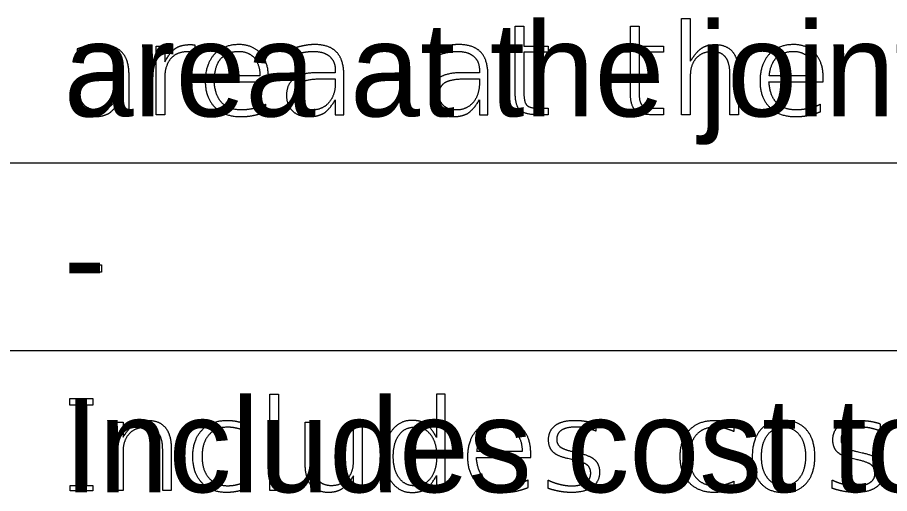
# Model space of a CAD drawing. Extents: x 0.11 to 2.72, y -0.17 to 1.89.
# Drawn here: x 1.1207 to 1.2367, y 1.339 to 1.4023 of the extents above; entities that cross this region are included whole.
import ezdxf

# ---------------------------------------------------------------- set-up
doc = ezdxf.new("R2010")
doc.units = 0
doc.layers.add('SheetGridMinor', color=7, linetype='Continuous')
doc.layers.add('SheetText', color=7, linetype='Continuous')

msp = doc.modelspace()

# ---------------------------------------------------------------- linework, layer by layer
at = {"layer": 'SheetGridMinor'}
for p, q in [((0.15035, 1.38302), (1.94912, 1.38302)), ((0.15035, 1.35802), (1.94912, 1.35802))]:
    msp.add_line(p, q, dxfattribs=at)
at = {"layer": 'SheetText'}
for p, q in [((1.14429, 1.39869), (1.14429, 1.39763)), ((1.12861, 1.39814), (1.12861, 1.3972)), ((1.15719, 1.39814), (1.15719, 1.3972)), ((1.17637, 1.39814), (1.17637, 1.3972)), ((1.15295, 1.39459), (1.14692, 1.39458)), ((1.22677, 1.39459), (1.22074, 1.39458)), ((1.15373, 1.38981), (1.15373, 1.39079)), ((1.22755, 1.38981), (1.22755, 1.39079)), ((1.22263, 1.34874), (1.22263, 1.34874)), ((1.15114, 1.34822), (1.15114, 1.34725)), ((1.19764, 1.34829), (1.19764, 1.34731)), ((1.216, 1.34822), (1.216, 1.34725)), ((1.22263, 1.34783), (1.22263, 1.34783)), ((1.23547, 1.34829), (1.23547, 1.34731)), ((1.1707, 1.34394), (1.1707, 1.34394)), ((1.18785, 1.34459), (1.18183, 1.34458)), ((1.19471, 1.34456), (1.19525, 1.34444)), ((1.23254, 1.34456), (1.23308, 1.34444)), ((1.19448, 1.34353), (1.19394, 1.34366)), ((1.23231, 1.34353), (1.23177, 1.34366)), ((1.15114, 1.34064), (1.15114, 1.33969)), ((1.18863, 1.33981), (1.18863, 1.34079)), ((1.19129, 1.33969), (1.19129, 1.3408)), ((1.216, 1.34064), (1.216, 1.33969)), ((1.22912, 1.33969), (1.22912, 1.3408))]:
    msp.add_line(p, q, dxfattribs=at)
for points in [[(1.21022, 1.39457), (1.21022, 1.3894), (1.20907, 1.3894), (1.20907, 1.40222), (1.21022, 1.40222), (1.21022, 1.39652)], [(1.18693, 1.39233), (1.18693, 1.39771), (1.18578, 1.39771), (1.18578, 1.39851), (1.18693, 1.39851), (1.18693, 1.40121), (1.18808, 1.40121), (1.18808, 1.39851), (1.1913, 1.39851), (1.1913, 1.39771), (1.18808, 1.39771), (1.18808, 1.39233)], [(1.20226, 1.39233), (1.20226, 1.39771), (1.20111, 1.39771), (1.20111, 1.39851), (1.20226, 1.39851), (1.20226, 1.40121), (1.20341, 1.40121), (1.20341, 1.39851), (1.20664, 1.39851), (1.20664, 1.39771), (1.20341, 1.39771), (1.20341, 1.39233)], [(1.14028, 1.39421), (1.14028, 1.3894), (1.13913, 1.3894), (1.13913, 1.39851), (1.14028, 1.39851), (1.14028, 1.39643)], [(1.1344, 1.39536), (1.1344, 1.39499), (1.13199, 1.39499)], [(1.16298, 1.39536), (1.16298, 1.39499), (1.16057, 1.39499)], [(1.18216, 1.39536), (1.18216, 1.39499), (1.17975, 1.39499)], [(1.13263, 1.39419), (1.1344, 1.39419), (1.1344, 1.39363)], [(1.1344, 1.39138), (1.1344, 1.3894), (1.13554, 1.3894), (1.13554, 1.39462)], [(1.14687, 1.39379), (1.15409, 1.39379), (1.15409, 1.39434)], [(1.16121, 1.39419), (1.16298, 1.39419), (1.16298, 1.39363)], [(1.16298, 1.39138), (1.16298, 1.3894), (1.16412, 1.3894), (1.16412, 1.39462)], [(1.18039, 1.39419), (1.18216, 1.39419), (1.18216, 1.39363)], [(1.18216, 1.39138), (1.18216, 1.3894), (1.1833, 1.3894), (1.1833, 1.39462)], [(1.21663, 1.39494), (1.21663, 1.3894), (1.21549, 1.3894), (1.21549, 1.39489)], [(1.22069, 1.39379), (1.22791, 1.39379), (1.22791, 1.39434)], [(1.18991, 1.39028), (1.1913, 1.39028), (1.1913, 1.3894), (1.18991, 1.3894)], [(1.20524, 1.39028), (1.20664, 1.39028), (1.20664, 1.3894), (1.20524, 1.3894)], [(1.17647, 1.34141), (1.17647, 1.3394), (1.17761, 1.3394), (1.17761, 1.35222), (1.17647, 1.35222), (1.17647, 1.34648)], [(1.13474, 1.34457), (1.13474, 1.3394), (1.13359, 1.3394), (1.13359, 1.34851), (1.13474, 1.34851), (1.13474, 1.34652)], [(1.15898, 1.34295), (1.15898, 1.34851), (1.16012, 1.34851), (1.16012, 1.34301)], [(1.1654, 1.34331), (1.1654, 1.34851), (1.16654, 1.34851), (1.16654, 1.3394), (1.1654, 1.3394), (1.1654, 1.34136)], [(1.14115, 1.34494), (1.14115, 1.3394), (1.14001, 1.3394), (1.14001, 1.34489)], [(1.18177, 1.34379), (1.18899, 1.34379), (1.18899, 1.34434)]]:
    msp.add_lwpolyline(points, dxfattribs=at)
for points in [[(1.12772, 1.36945), (1.13188, 1.36945), (1.13188, 1.36847), (1.12772, 1.36847)], [(1.15429, 1.35222), (1.15543, 1.35222), (1.15543, 1.3394), (1.15429, 1.3394)], [(1.12858, 1.35075), (1.12767, 1.35075), (1.12767, 1.35166), (1.13072, 1.35166), (1.13072, 1.35075), (1.12987, 1.35075), (1.12987, 1.34007), (1.13072, 1.34007), (1.13072, 1.33935), (1.12771, 1.33935), (1.12771, 1.34007), (1.12858, 1.34007)]]:
    msp.add_lwpolyline(points, close=True, dxfattribs=at)
for points in [[(1.13011, 1.39857), (1.12932, 1.39841), (1.12861, 1.39814)], [(1.13164, 1.39874), (1.1309, 1.39874), (1.13011, 1.39857)], [(1.13458, 1.39773), (1.13362, 1.39874), (1.13164, 1.39874)], [(1.14188, 1.39834), (1.14262, 1.39874), (1.14371, 1.39874)], [(1.14371, 1.39874), (1.14386, 1.39874), (1.14404, 1.39872)], [(1.14404, 1.39872), (1.14423, 1.39869), (1.14429, 1.39869)], [(1.15014, 1.39874), (1.14809, 1.39874), (1.14688, 1.39743)], [(1.15303, 1.39756), (1.15197, 1.39874), (1.15014, 1.39874)], [(1.15869, 1.39857), (1.1579, 1.39841), (1.15719, 1.39814)], [(1.16022, 1.39874), (1.15948, 1.39874), (1.15869, 1.39857)], [(1.16316, 1.39773), (1.16219, 1.39874), (1.16022, 1.39874)], [(1.17787, 1.39857), (1.17708, 1.39841), (1.17637, 1.39814)], [(1.1794, 1.39874), (1.17866, 1.39874), (1.17787, 1.39857)], [(1.18234, 1.39773), (1.18138, 1.39874), (1.1794, 1.39874)], [(1.21186, 1.39834), (1.21258, 1.39874), (1.21351, 1.39874)], [(1.21351, 1.39874), (1.21505, 1.39874), (1.21584, 1.39779)], [(1.22396, 1.39874), (1.22191, 1.39874), (1.2207, 1.39743)], [(1.22685, 1.39756), (1.22579, 1.39874), (1.22396, 1.39874)], [(1.12861, 1.3972), (1.12904, 1.39743), (1.12984, 1.39763)], [(1.12984, 1.39763), (1.13064, 1.39783), (1.13148, 1.39783)], [(1.13148, 1.39783), (1.13284, 1.39783), (1.13362, 1.39719)], [(1.13554, 1.39462), (1.13554, 1.39672), (1.13458, 1.39773)], [(1.14028, 1.39643), (1.14114, 1.39794), (1.14188, 1.39834)], [(1.14325, 1.39777), (1.14182, 1.39777), (1.14105, 1.39683)], [(1.14399, 1.39769), (1.14365, 1.39777), (1.14325, 1.39777)], [(1.14429, 1.39762), (1.14424, 1.39762), (1.14399, 1.39769)], [(1.14429, 1.39763), (1.14429, 1.39762), (1.14429, 1.39762)], [(1.14688, 1.39743), (1.14568, 1.39611), (1.14568, 1.39386)], [(1.14791, 1.39704), (1.14876, 1.39783), (1.15016, 1.39783)], [(1.15016, 1.39783), (1.15141, 1.39783), (1.15217, 1.397)], [(1.15409, 1.39434), (1.15409, 1.39639), (1.15303, 1.39756)], [(1.15719, 1.3972), (1.15761, 1.39743), (1.15841, 1.39763)], [(1.15841, 1.39763), (1.15921, 1.39783), (1.16006, 1.39783)], [(1.16006, 1.39783), (1.16142, 1.39783), (1.1622, 1.39719)], [(1.16412, 1.39462), (1.16412, 1.39672), (1.16316, 1.39773)], [(1.17637, 1.3972), (1.1768, 1.39743), (1.1776, 1.39763)], [(1.1776, 1.39763), (1.1784, 1.39783), (1.17924, 1.39783)], [(1.17924, 1.39783), (1.1806, 1.39783), (1.18138, 1.39719)], [(1.1833, 1.39462), (1.1833, 1.39672), (1.18234, 1.39773)], [(1.21022, 1.39652), (1.21115, 1.39794), (1.21186, 1.39834)], [(1.21316, 1.3978), (1.2118, 1.3978), (1.21101, 1.39693)], [(1.21491, 1.39706), (1.21432, 1.3978), (1.21316, 1.3978)], [(1.21584, 1.39779), (1.21663, 1.39684), (1.21663, 1.39494)], [(1.2207, 1.39743), (1.2195, 1.39611), (1.2195, 1.39386)], [(1.22174, 1.39704), (1.22258, 1.39783), (1.22398, 1.39783)], [(1.22398, 1.39783), (1.22523, 1.39783), (1.22599, 1.397)], [(1.22791, 1.39434), (1.22791, 1.39639), (1.22685, 1.39756)], [(1.13362, 1.39719), (1.1344, 1.39654), (1.1344, 1.39536)], [(1.14105, 1.39683), (1.14028, 1.3959), (1.14028, 1.39421)], [(1.14692, 1.39458), (1.14707, 1.39624), (1.14791, 1.39704)], [(1.15217, 1.397), (1.15293, 1.39617), (1.15295, 1.39459)], [(1.1622, 1.39719), (1.16298, 1.39654), (1.16298, 1.39536)], [(1.18138, 1.39719), (1.18216, 1.39654), (1.18216, 1.39536)], [(1.21101, 1.39693), (1.21022, 1.39605), (1.21022, 1.39457)], [(1.21549, 1.39489), (1.21549, 1.39632), (1.21491, 1.39706)], [(1.22074, 1.39458), (1.22089, 1.39624), (1.22174, 1.39704)], [(1.22599, 1.397), (1.22675, 1.39617), (1.22677, 1.39459)], [(1.13199, 1.39499), (1.12992, 1.39499), (1.12892, 1.39423)], [(1.16057, 1.39499), (1.1585, 1.39499), (1.15749, 1.39423)], [(1.17975, 1.39499), (1.17768, 1.39499), (1.17668, 1.39423)], [(1.12892, 1.39423), (1.12791, 1.39347), (1.12791, 1.39196)], [(1.12986, 1.39371), (1.13067, 1.39419), (1.13263, 1.39419)], [(1.14568, 1.39386), (1.14568, 1.39168), (1.14695, 1.39041)], [(1.15749, 1.39423), (1.15649, 1.39347), (1.15649, 1.39196)], [(1.15844, 1.39371), (1.15925, 1.39419), (1.16121, 1.39419)], [(1.17668, 1.39423), (1.17567, 1.39347), (1.17567, 1.39196)], [(1.17762, 1.39371), (1.17843, 1.39419), (1.18039, 1.39419)], [(1.2195, 1.39386), (1.2195, 1.39168), (1.22077, 1.39041)], [(1.12905, 1.39206), (1.12905, 1.39323), (1.12986, 1.39371)], [(1.1344, 1.39363), (1.1344, 1.39202), (1.13356, 1.39103)], [(1.14793, 1.39096), (1.147, 1.39187), (1.14687, 1.39379)], [(1.15763, 1.39206), (1.15763, 1.39323), (1.15844, 1.39371)], [(1.16298, 1.39363), (1.16298, 1.39202), (1.16214, 1.39103)], [(1.17681, 1.39206), (1.17681, 1.39323), (1.17762, 1.39371)], [(1.18216, 1.39363), (1.18216, 1.39202), (1.18132, 1.39103)], [(1.22175, 1.39096), (1.22082, 1.39187), (1.22069, 1.39379)], [(1.12791, 1.39196), (1.12791, 1.39067), (1.12871, 1.38991)], [(1.12967, 1.39058), (1.12905, 1.39113), (1.12905, 1.39206)], [(1.15649, 1.39196), (1.15649, 1.39067), (1.15729, 1.38991)], [(1.15824, 1.39058), (1.15763, 1.39113), (1.15763, 1.39206)], [(1.17567, 1.39196), (1.17567, 1.39067), (1.17647, 1.38991)], [(1.17743, 1.39058), (1.17681, 1.39113), (1.17681, 1.39206)], [(1.18755, 1.39001), (1.18693, 1.39062), (1.18693, 1.39233)], [(1.18808, 1.39233), (1.18808, 1.39107), (1.18846, 1.39068)], [(1.20289, 1.39001), (1.20226, 1.39062), (1.20226, 1.39233)], [(1.20341, 1.39233), (1.20341, 1.39107), (1.20379, 1.39068)], [(1.13131, 1.39004), (1.13028, 1.39004), (1.12967, 1.39058)], [(1.13356, 1.39103), (1.13271, 1.39004), (1.13131, 1.39004)], [(1.13275, 1.38954), (1.1335, 1.38992), (1.1344, 1.39138)], [(1.14695, 1.39041), (1.14822, 1.38915), (1.15041, 1.38915)], [(1.15051, 1.39005), (1.14886, 1.39005), (1.14793, 1.39096)], [(1.15373, 1.39079), (1.15318, 1.39051), (1.15231, 1.39028)], [(1.15989, 1.39004), (1.15886, 1.39004), (1.15824, 1.39058)], [(1.16214, 1.39103), (1.16129, 1.39004), (1.15989, 1.39004)], [(1.16133, 1.38954), (1.16208, 1.38992), (1.16298, 1.39138)], [(1.17907, 1.39004), (1.17804, 1.39004), (1.17743, 1.39058)], [(1.18132, 1.39103), (1.18047, 1.39004), (1.17907, 1.39004)], [(1.18051, 1.38954), (1.18126, 1.38992), (1.18216, 1.39138)], [(1.18846, 1.39068), (1.18884, 1.39028), (1.18991, 1.39028)], [(1.20379, 1.39068), (1.20417, 1.39028), (1.20524, 1.39028)], [(1.22077, 1.39041), (1.22204, 1.38915), (1.22423, 1.38915)], [(1.22433, 1.39005), (1.22268, 1.39005), (1.22175, 1.39096)], [(1.22755, 1.39079), (1.227, 1.39051), (1.22613, 1.39028)], [(1.12871, 1.38991), (1.12951, 1.38915), (1.13089, 1.38915)], [(1.13089, 1.38915), (1.132, 1.38915), (1.13275, 1.38954)], [(1.15041, 1.38915), (1.1513, 1.38915), (1.15216, 1.38933)], [(1.15231, 1.39028), (1.15144, 1.39005), (1.15051, 1.39005)], [(1.15216, 1.38933), (1.15303, 1.38952), (1.15373, 1.38981)], [(1.15729, 1.38991), (1.15809, 1.38915), (1.15947, 1.38915)], [(1.15947, 1.38915), (1.16058, 1.38915), (1.16133, 1.38954)], [(1.17647, 1.38991), (1.17727, 1.38915), (1.17865, 1.38915)], [(1.17865, 1.38915), (1.17976, 1.38915), (1.18051, 1.38954)], [(1.18991, 1.3894), (1.18818, 1.3894), (1.18755, 1.39001)], [(1.20524, 1.3894), (1.20351, 1.3894), (1.20289, 1.39001)], [(1.22423, 1.38915), (1.22512, 1.38915), (1.22598, 1.38933)], [(1.22613, 1.39028), (1.22526, 1.39005), (1.22433, 1.39005)], [(1.22598, 1.38933), (1.22685, 1.38952), (1.22755, 1.38981)], [(1.13639, 1.34834), (1.1371, 1.34874), (1.13804, 1.34874)], [(1.13804, 1.34874), (1.13958, 1.34874), (1.14037, 1.34779)], [(1.14525, 1.34746), (1.14647, 1.34874), (1.1486, 1.34874)], [(1.1486, 1.34874), (1.1493, 1.34874), (1.14997, 1.34859)], [(1.14997, 1.34859), (1.15064, 1.34845), (1.15114, 1.34822)], [(1.1732, 1.34874), (1.17157, 1.34874), (1.17054, 1.34743)], [(1.1749, 1.34835), (1.1742, 1.34874), (1.1732, 1.34874)], [(1.18504, 1.34874), (1.18299, 1.34874), (1.18179, 1.34743)], [(1.18793, 1.34756), (1.18687, 1.34874), (1.18504, 1.34874)], [(1.19224, 1.34806), (1.19312, 1.34874), (1.19481, 1.34874)], [(1.19481, 1.34874), (1.19566, 1.34874), (1.1964, 1.34861)], [(1.1964, 1.34861), (1.19715, 1.34849), (1.19764, 1.34829)], [(1.21011, 1.34746), (1.21133, 1.34874), (1.21346, 1.34874)], [(1.21346, 1.34874), (1.21416, 1.34874), (1.21483, 1.34859)], [(1.21483, 1.34859), (1.2155, 1.34845), (1.216, 1.34822)], [(1.22263, 1.34874), (1.22067, 1.34874), (1.21957, 1.34748)], [(1.22569, 1.34748), (1.22458, 1.34874), (1.22263, 1.34874)], [(1.23007, 1.34806), (1.23095, 1.34874), (1.23263, 1.34874)], [(1.23263, 1.34874), (1.23349, 1.34874), (1.23423, 1.34861)], [(1.23423, 1.34861), (1.23498, 1.34849), (1.23547, 1.34829)], [(1.13474, 1.34652), (1.13567, 1.34794), (1.13639, 1.34834)], [(1.13769, 1.3478), (1.13633, 1.3478), (1.13553, 1.34693)], [(1.13943, 1.34706), (1.13885, 1.3478), (1.13769, 1.3478)], [(1.14037, 1.34779), (1.14115, 1.34684), (1.14115, 1.34494)], [(1.14402, 1.34394), (1.14402, 1.34619), (1.14525, 1.34746)], [(1.14867, 1.34783), (1.14706, 1.34783), (1.14615, 1.3468)], [(1.15007, 1.34764), (1.14938, 1.34783), (1.14867, 1.34783)], [(1.15114, 1.34725), (1.15077, 1.34745), (1.15007, 1.34764)], [(1.17054, 1.34743), (1.16951, 1.34611), (1.16951, 1.34394)], [(1.17146, 1.3468), (1.17223, 1.34785), (1.17358, 1.34785)], [(1.17358, 1.34785), (1.17493, 1.34785), (1.1757, 1.3468)], [(1.17647, 1.34648), (1.17561, 1.34796), (1.1749, 1.34835)], [(1.18179, 1.34743), (1.18058, 1.34611), (1.18058, 1.34386)], [(1.18282, 1.34704), (1.18366, 1.34783), (1.18506, 1.34783)], [(1.18506, 1.34783), (1.18631, 1.34783), (1.18707, 1.347)], [(1.18899, 1.34434), (1.18899, 1.34639), (1.18793, 1.34756)], [(1.19136, 1.34614), (1.19136, 1.34738), (1.19224, 1.34806)], [(1.19311, 1.34745), (1.19245, 1.34704), (1.19245, 1.34621)], [(1.19499, 1.34785), (1.19377, 1.34785), (1.19311, 1.34745)], [(1.19653, 1.34768), (1.19579, 1.34785), (1.19499, 1.34785)], [(1.19764, 1.34731), (1.19727, 1.3475), (1.19653, 1.34768)], [(1.20888, 1.34394), (1.20888, 1.34619), (1.21011, 1.34746)], [(1.21353, 1.34783), (1.21191, 1.34783), (1.21101, 1.3468)], [(1.21493, 1.34764), (1.21424, 1.34783), (1.21353, 1.34783)], [(1.216, 1.34725), (1.21563, 1.34745), (1.21493, 1.34764)], [(1.21957, 1.34748), (1.21847, 1.34622), (1.21847, 1.34394)], [(1.22048, 1.34678), (1.22126, 1.34783), (1.22263, 1.34783)], [(1.22263, 1.34783), (1.22399, 1.34783), (1.22478, 1.34677)], [(1.2268, 1.34394), (1.2268, 1.34622), (1.22569, 1.34748)], [(1.22919, 1.34614), (1.22919, 1.34738), (1.23007, 1.34806)], [(1.23094, 1.34745), (1.23028, 1.34704), (1.23028, 1.34621)], [(1.23282, 1.34785), (1.2316, 1.34785), (1.23094, 1.34745)], [(1.23435, 1.34768), (1.23361, 1.34785), (1.23282, 1.34785)], [(1.23547, 1.34731), (1.2351, 1.3475), (1.23435, 1.34768)], [(1.13553, 1.34693), (1.13474, 1.34605), (1.13474, 1.34457)], [(1.14001, 1.34489), (1.14001, 1.34632), (1.13943, 1.34706)], [(1.14615, 1.3468), (1.14525, 1.34576), (1.14525, 1.34394)], [(1.1707, 1.34394), (1.1707, 1.34574), (1.17146, 1.3468)], [(1.1757, 1.3468), (1.17647, 1.34574), (1.17647, 1.34394)], [(1.18183, 1.34458), (1.18197, 1.34624), (1.18282, 1.34704)], [(1.18707, 1.347), (1.18784, 1.34617), (1.18785, 1.34459)], [(1.21101, 1.3468), (1.21011, 1.34576), (1.21011, 1.34394)], [(1.2197, 1.34394), (1.2197, 1.34572), (1.22048, 1.34678)], [(1.22478, 1.34677), (1.22556, 1.34571), (1.22556, 1.34394)], [(1.19195, 1.34454), (1.19136, 1.34513), (1.19136, 1.34614)], [(1.19245, 1.34621), (1.19245, 1.34555), (1.19293, 1.3452)], [(1.19293, 1.3452), (1.1934, 1.34485), (1.19471, 1.34456)], [(1.22978, 1.34454), (1.22919, 1.34513), (1.22919, 1.34614)], [(1.23028, 1.34621), (1.23028, 1.34555), (1.23075, 1.3452)], [(1.23075, 1.3452), (1.23123, 1.34485), (1.23254, 1.34456)], [(1.14523, 1.34044), (1.14402, 1.34173), (1.14402, 1.34394)], [(1.14525, 1.34394), (1.14525, 1.34212), (1.14615, 1.34109)], [(1.16951, 1.34394), (1.16951, 1.34177), (1.17054, 1.34046)], [(1.17146, 1.34109), (1.1707, 1.34215), (1.1707, 1.34394)], [(1.17647, 1.34394), (1.17647, 1.34215), (1.1757, 1.34109)], [(1.19394, 1.34366), (1.19254, 1.34396), (1.19195, 1.34454)], [(1.19525, 1.34444), (1.19686, 1.34409), (1.19751, 1.34349)], [(1.21009, 1.34044), (1.20888, 1.34173), (1.20888, 1.34394)], [(1.21011, 1.34394), (1.21011, 1.34212), (1.21101, 1.34109)], [(1.21847, 1.34394), (1.21847, 1.34168), (1.21957, 1.34041)], [(1.22047, 1.34111), (1.2197, 1.34216), (1.2197, 1.34394)], [(1.22556, 1.34394), (1.22556, 1.34217), (1.22478, 1.34111)], [(1.22569, 1.34041), (1.2268, 1.34168), (1.2268, 1.34394)], [(1.23177, 1.34366), (1.23037, 1.34396), (1.22978, 1.34454)], [(1.23308, 1.34444), (1.23469, 1.34409), (1.23533, 1.34349)], [(1.15977, 1.3401), (1.15898, 1.34106), (1.15898, 1.34295)], [(1.16012, 1.34301), (1.16012, 1.34158), (1.1607, 1.34083)], [(1.1646, 1.34096), (1.1654, 1.34183), (1.1654, 1.34331)], [(1.18058, 1.34386), (1.18058, 1.34168), (1.18185, 1.34041)], [(1.18283, 1.34096), (1.1819, 1.34187), (1.18177, 1.34379)], [(1.19648, 1.34282), (1.19599, 1.34321), (1.19448, 1.34353)], [(1.19697, 1.3417), (1.19697, 1.34244), (1.19648, 1.34282)], [(1.19751, 1.34349), (1.19815, 1.34289), (1.19815, 1.34181)], [(1.23431, 1.34282), (1.23382, 1.34321), (1.23231, 1.34353)], [(1.2348, 1.3417), (1.2348, 1.34244), (1.23431, 1.34282)], [(1.23533, 1.34349), (1.23598, 1.34289), (1.23598, 1.34181)], [(1.1963, 1.34046), (1.19697, 1.34089), (1.19697, 1.3417)], [(1.19815, 1.34181), (1.19815, 1.3406), (1.19717, 1.33987)], [(1.23412, 1.34046), (1.2348, 1.34089), (1.2348, 1.3417)], [(1.23598, 1.34181), (1.23598, 1.3406), (1.235, 1.33987)], [(1.14615, 1.34109), (1.14706, 1.34005), (1.14867, 1.34005)], [(1.15007, 1.34024), (1.15077, 1.34044), (1.15114, 1.34064)], [(1.1607, 1.34083), (1.16128, 1.34009), (1.16244, 1.34009)], [(1.16244, 1.34009), (1.1638, 1.34009), (1.1646, 1.34096)], [(1.1654, 1.34136), (1.16446, 1.33994), (1.16375, 1.33955)], [(1.17054, 1.34046), (1.17157, 1.33915), (1.1732, 1.33915)], [(1.17358, 1.34003), (1.17223, 1.34003), (1.17146, 1.34109)], [(1.1757, 1.34109), (1.17493, 1.34003), (1.17358, 1.34003)], [(1.1749, 1.33954), (1.17561, 1.33992), (1.17647, 1.34141)], [(1.18541, 1.34005), (1.18377, 1.34005), (1.18283, 1.34096)], [(1.18863, 1.34079), (1.18808, 1.34051), (1.18721, 1.34028)], [(1.19129, 1.3408), (1.19187, 1.3405), (1.19274, 1.34027)], [(1.19446, 1.34003), (1.19562, 1.34003), (1.1963, 1.34046)], [(1.21101, 1.34109), (1.21191, 1.34005), (1.21353, 1.34005)], [(1.21493, 1.34024), (1.21563, 1.34044), (1.216, 1.34064)], [(1.22263, 1.34005), (1.22125, 1.34005), (1.22047, 1.34111)], [(1.22478, 1.34111), (1.22399, 1.34005), (1.22263, 1.34005)], [(1.22912, 1.3408), (1.2297, 1.3405), (1.23057, 1.34027)], [(1.23229, 1.34003), (1.23345, 1.34003), (1.23412, 1.34046)], [(1.1485, 1.33915), (1.14644, 1.33915), (1.14523, 1.34044)], [(1.14995, 1.3393), (1.14927, 1.33915), (1.1485, 1.33915)], [(1.14867, 1.34005), (1.14938, 1.34005), (1.15007, 1.34024)], [(1.15114, 1.33969), (1.15063, 1.33945), (1.14995, 1.3393)], [(1.16211, 1.33915), (1.16057, 1.33915), (1.15977, 1.3401)], [(1.16375, 1.33955), (1.16305, 1.33915), (1.16211, 1.33915)], [(1.1732, 1.33915), (1.1742, 1.33915), (1.1749, 1.33954)], [(1.18185, 1.34041), (1.18312, 1.33915), (1.18532, 1.33915)], [(1.18532, 1.33915), (1.1862, 1.33915), (1.18707, 1.33933)], [(1.18721, 1.34028), (1.18634, 1.34005), (1.18541, 1.34005)], [(1.18707, 1.33933), (1.18793, 1.33952), (1.18863, 1.33981)], [(1.19286, 1.33929), (1.19205, 1.33944), (1.19129, 1.33969)], [(1.19274, 1.34027), (1.19361, 1.34003), (1.19446, 1.34003)], [(1.19442, 1.33915), (1.19368, 1.33915), (1.19286, 1.33929)], [(1.19717, 1.33987), (1.1962, 1.33915), (1.19442, 1.33915)], [(1.21336, 1.33915), (1.2113, 1.33915), (1.21009, 1.34044)], [(1.21481, 1.3393), (1.21413, 1.33915), (1.21336, 1.33915)], [(1.21353, 1.34005), (1.21424, 1.34005), (1.21493, 1.34024)], [(1.216, 1.33969), (1.21549, 1.33945), (1.21481, 1.3393)], [(1.21957, 1.34041), (1.22067, 1.33915), (1.22263, 1.33915)], [(1.22263, 1.33915), (1.22458, 1.33915), (1.22569, 1.34041)], [(1.23069, 1.33929), (1.22988, 1.33944), (1.22912, 1.33969)], [(1.23057, 1.34027), (1.23143, 1.34003), (1.23229, 1.34003)], [(1.23225, 1.33915), (1.2315, 1.33915), (1.23069, 1.33929)], [(1.235, 1.33987), (1.23402, 1.33915), (1.23225, 1.33915)]]:
    msp.add_open_spline(points, degree=2, dxfattribs=at)

# ---------------------------------------------------------------- texts
for s, p in [('area at the joints.', (1.12686, 1.38918)), ('-', (1.12686, 1.36418)), ('Includes cost to furnish and install 2.4 CY of flowable mortar at west end of south ', (1.12686, 1.33918))]:
    msp.add_text(s, height=0.0125, dxfattribs=at).set_placement(p)

doc.saveas('drawing.dxf')
